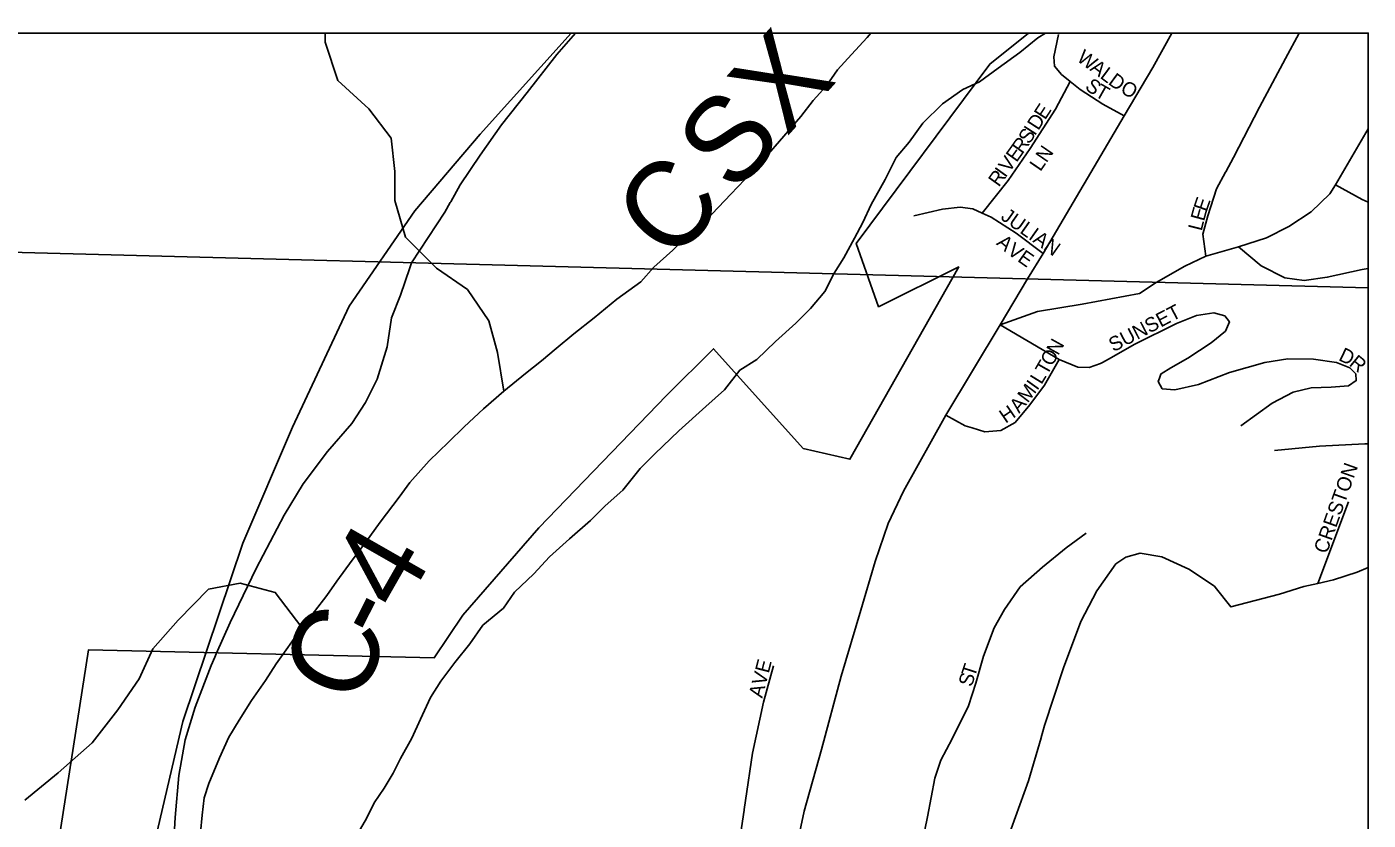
# Model space of a CAD drawing. Extents: x -84548 to 2262448, y -162180 to 525962.
# Drawn here: x 63175 to 67849, y 168130 to 170894 of the extents above; entities that cross this region are included whole.
import ezdxf

# ---------------------------------------------------------------- set-up
doc = ezdxf.new("R2010")
doc.units = 0
for name, color, linetype in [('GM_X_Corporation', 7, 'Continuous'), ('GM_X_County', 7, 'Continuous'), ('GM_X_County_Road', 7, 'Continuous'), ('GM_X_Hydro', 7, 'Continuous'), ('GM_X_Interstate_Location', 7, 'Continuous'), ('GM_X_Major_Lake_Text', 7, 'Continuous'), ('GM_X_Minor_River_Text', 7, 'Continuous'), ('GM_X_State_Route', 7, 'Continuous'), ('GM_X_Township_Subdivision_Text', 7, 'Continuous'), ('GM_X_Unincorporated_Location', 7, 'Continuous'), ('GM_X_US_Location', 7, 'Continuous'), ('GM_X_US_Route', 7, 'Continuous')]:
    doc.layers.add(name, color=color, linetype=linetype)

msp = doc.modelspace()

# ---------------------------------------------------------------- linework, layer by layer
at = {"layer": 'GM_X_County'}
for p, q in [((31945.4, 170872.5), (67849.4, 170872.5)), ((67849.4, 170872.5), (67849.4, 134968.5))]:
    msp.add_line(p, q, dxfattribs=at)
at = {"layer": 'GM_X_Hydro'}
msp.add_line((62491.5, 170125.7), (67849.4, 169984.2), dxfattribs=at)
at = {"layer": 'GM_X_Interstate_Location'}
for points in [[(64516.6, 168415.6), (64547.6, 168482.3), (64582.4, 168557.1), (64617.6, 168613.9), (64666.6, 168678.8), (64719.7, 168743.9), (64764.7, 168808.8), (64835.9, 168868.1), (64875, 168924.9), (64942.1, 168988.2), (64997.2, 169047.3), (65066.3, 169110.6), (65139.4, 169174), (65190.7, 169224.9), (65251.9, 169280.1), (65312.8, 169355.3), (65364, 169406.3), (65446.9, 169485.9), (65541.7, 169571.6), (65606.8, 169628.9), (65659.8, 169697.9), (65719.3, 169735), (65784.4, 169798.2), (65855.5, 169861.6), (65906.7, 169912.6), (65955.9, 169971.5), (65988.9, 170036.3), (66022.1, 170088.9), (66059.1, 170157.8), (66088.2, 170212.4), (66117.3, 170275.1), (66166, 170362.1), (66204.8, 170439), (66250, 170491.9), (66297.1, 170558.8), (66366.1, 170626.1), (66437.4, 170675.4), (66495, 170702.4), (66560.4, 170749.6), (66635.6, 170805), (66698.8, 170856.2), (66725.3, 170872.5)], [(66116.1, 170872.5), (66104.2, 170856.6), (66049, 170797.6), (65999.8, 170744.6), (65960.6, 170687.8), (65915.4, 170636.9), (65872.2, 170582.1), (65813.2, 170512.9), (65744.4, 170433.6), (65677.4, 170362.3), (65628.2, 170311.3), (65563.2, 170242.1), (65492.1, 170178.7), (65427, 170115.5), (65359.8, 170056.2), (65314.6, 170005.3), (65231.4, 169945.8), (65152.4, 169880.3), (65081.1, 169825), (65019.9, 169773.9), (64968.5, 169730.9), (64913.1, 169685.9)], [(64913.1, 169685.9), (64838, 169624.5), (64766.9, 169563.2), (64699.8, 169499.9), (64644.6, 169446.9), (64577.5, 169381.6), (64510.6, 169306.3), (64473.4, 169255.5), (64406.7, 169168.2), (64355.7, 169097.1), (64308.6, 169036.2), (64255.7, 168963.1), (64220.5, 168912.4), (64177.3, 168857.5), (64134.1, 168800.7), (64085.1, 168731.7), (64044, 168674.8), (64006.8, 168616.1), (63957.9, 168547), (63914.9, 168478.2), (63879.8, 168419.4), (63846.9, 168346.7), (63810.2, 168257.8), (63793, 168207.4), (63785.9, 168147.1), (63780.9, 168086.8)], [(64329.6, 168085.6), (64358.8, 168136.2), (64386, 168190.8), (64421.2, 168241.6), (64452.4, 168294.2), (64477.7, 168344.8), (64516.6, 168415.6)]]:
    msp.add_lwpolyline(points, dxfattribs=at)
at = {"layer": 'GM_X_Major_Lake_Text'}
msp.add_lwpolyline([(66091.5, 166671.9), (66031.4, 166747.7), (65948.4, 166868), (65891.6, 166973.8), (65846.9, 167057.6), (65841.5, 167237.8), (65846, 167426.1), (65842.2, 167658.4), (65844.8, 167832.7), (65849.7, 167998.1), (65884.3, 168161.5), (65944.7, 168376.3), (66012.8, 168631.2), (66081.1, 168862), (66131.8, 169030.7), (66176.8, 169163.2), (66230, 169275.8), (66377.7, 169540.7), (66566.6, 169855.9), (66662.7, 170015.6), (66716.4, 170104.7), (66999.5, 170583.9), (67099.2, 170752.6), (67165.1, 170872.5)], dxfattribs=at)
at = {"layer": 'GM_X_Minor_River_Text'}
for points in [[(64652.5, 170284.6), (64685.9, 170343.6), (64755.7, 170447.3), (64829.5, 170553), (64919.1, 170665.1), (65022.3, 170797.5), (65087.7, 170872.5)], [(64509.8, 170054.3), (64515.9, 170072.3), (64631.9, 170248.3), (64650.8, 170281.7), (64652.5, 170284.6)], [(63835.6, 168709.1), (63884.3, 168818.1), (63974.3, 169006.4), (64072.3, 169192.8), (64138, 169302.3), (64223.7, 169414.3), (64307.6, 169512.3), (64356, 169585.4), (64396.3, 169666.4), (64431.3, 169779.5), (64446, 169879.6), (64477.4, 169959.3), (64509.8, 170054.3)]]:
    msp.add_lwpolyline(points, dxfattribs=at)
at = {"layer": 'GM_X_State_Route'}
for points in [[(64838, 169624.5), (64815.1, 169759.9), (64785.2, 169870.2), (64711.2, 169978.5), (64603.2, 170052.7), (64495.2, 170161.1), (64457.3, 170289.5), (64457.3, 170389.8), (64445.3, 170506.1), (64367.3, 170608.4), (64259.4, 170706.7), (64215.4, 170841.1), (64215.4, 170872.5)], [(64134.1, 168800.7), (64041.1, 168923.3), (63919.1, 168955.4), (63809.1, 168935.3), (63703.1, 168827), (63615.1, 168726.7), (63567.1, 168622.4), (63493, 168514.1), (63403, 168399.7), (63285, 168295.4), (63169, 168199.1)]]:
    msp.add_lwpolyline(points, dxfattribs=at)
at = {"layer": 'GM_X_Township_Subdivision_Text'}
msp.add_lwpolyline([(67849.4, 159186.1), (67849.4, 170872.5), (66665.9, 170872.5), (66530.9, 170764.5), (66064.8, 170139.6), (66143.6, 169918.7), (66422.6, 170057.4), (66043.7, 169387.3), (65881.1, 169424.9), (65568, 169772.7), (65404.7, 169609.4), (64960, 169148.9), (64695, 168844), (64595.1, 168695.9), (63390, 168723.1), (63175.6, 167343.1), (63083.4, 167321.6), (63027, 167263.7), (62990.6, 167201.8), (61806.2, 167434.3), (60891.2, 167434.3), (60993.6, 168267), (60975.5, 168788.1), (57658.2, 168787.9)], dxfattribs=at)
at = {"layer": 'GM_X_Unincorporated_Location'}
msp.add_lwpolyline([(65797.8, 163683.4), (64931.5, 164490.9), (64776, 164625.2), (64522.4, 164772.8), (64164.9, 165001.2), (63947.4, 165219.4), (63665.8, 165488.3), (63484.8, 165649.3), (63354.2, 165815.8), (63299.3, 165969.2), (63259.3, 166117.3), (63278.1, 166434.9), (63339.6, 166846.8), (63719, 168473.8), (63928.7, 169095), (64101.1, 169498.7), (64298.3, 169920.8), (64528, 170252.9), (64755.1, 170520.2), (65072.7, 170872.5)], dxfattribs=at)
at = {"layer": 'GM_X_US_Location'}
for points in [[(66769.8, 170867.9), (66754.6, 170789.6), (66756.9, 170757.6), (66781.2, 170727.7), (66810.8, 170704.1), (66845.8, 170676.3), (66924.3, 170624.9), (66999.5, 170583.9)], [(67352.4, 170387.4), (67353.3, 170389.1), (67380.3, 170438.9), (67470.6, 170614.1), (67560.9, 170783.3), (67608.5, 170872.5)], [(66504.4, 170244.9), (66594.8, 170359.2), (66671.7, 170470.2), (66760.4, 170607.3), (66810.8, 170704.1)], [(66566.6, 169855.9), (66697.2, 169902.7), (66852.3, 169927.6), (67052.8, 169964.9), (67110.7, 170003.7), (67210, 170060.6), (67284, 170094.6), (67397.6, 170128.1), (67495.1, 170159.5), (67572.7, 170198.3), (67650.2, 170249.2), (67715.6, 170311.9), (67735, 170344), (67849.4, 170538.2)], [(67284, 170094.6), (67272.9, 170171.4), (67290.3, 170235.7), (67321.3, 170330.2), (67352.4, 170387.4)], [(67735, 170344), (67827.9, 170293), (67849.4, 170283.6)], [(66265.9, 170235.8), (66365.7, 170258.8), (66427.7, 170265.4), (66471.7, 170259.9), (66504.4, 170244.9), (66536.1, 170230.4), (66622.6, 170175.1), (66716.4, 170104.7)], [(67397.6, 170128.1), (67476, 170061.1), (67558.5, 170019.8), (67626.6, 170010.5), (67706.5, 170021.3), (67828.3, 170048.5), (67849.4, 170052)], [(66923.7, 169724.8), (66944.8, 169736.6), (67036.6, 169788.4), (67181.9, 169859.9), (67251.7, 169888.6), (67311.6, 169897.2), (67349.7, 169887.6), (67365.9, 169865.7), (67352.2, 169833.5), (67302.6, 169792.9), (67221.1, 169740.1), (67161.4, 169705.4), (67127.6, 169685.1), (67127, 169683.4)], [(66566.6, 169855.9), (66660.3, 169800.8), (66772.5, 169735.1), (66837.3, 169708.3), (66877.3, 169706.7), (66917.2, 169721.1), (66923.7, 169724.8)], [(66569.4, 169487.3), (66619.1, 169515.8), (66670.6, 169576.5), (66721.9, 169645.1), (66772.5, 169735.1)], [(67127, 169683.4), (67121.8, 169669.4), (67117.9, 169658.9), (67132.1, 169633), (67176.2, 169629.4), (67258, 169648.2), (67365.7, 169689.4), (67489.4, 169724.6), (67569.3, 169737.4), (67659.3, 169736.3), (67739.4, 169725), (67785.6, 169705.4), (67805.9, 169685.6), (67808.1, 169661.6), (67780.3, 169643.2), (67720.3, 169638.7), (67650.3, 169636), (67588.4, 169621.4), (67514.8, 169582.6), (67405.5, 169503.4)], [(66377.7, 169540.7), (66445.2, 169504.1), (66469.5, 169496.5)], [(66469.5, 169496.5), (66469.6, 169496.5), (66513.4, 169482.8), (66569.4, 169487.3)], [(67522.4, 169418.3), (67679.5, 169432.8), (67837.5, 169441.7), (67849.4, 169440.9)], [(67673.4, 168955.1), (67780.3, 169238.5)], [(66360.5, 168338.6), (66360.7, 168339.1), (66400, 168413.6), (66456.9, 168528.4), (66482.1, 168606.8), (66509.2, 168701.2), (66546.2, 168799.8), (66581.6, 168864.2), (66636.8, 168942.9), (66714.1, 169011.8), (66797.5, 169078.7), (66867, 169129.5)], [(66709.5, 168416.4), (66709.9, 168418), (66722.1, 168459.9), (66788.1, 168661), (66848.6, 168821.9), (66903.5, 168928.6), (66970.6, 169023.5), (67004.4, 169045.9), (67054.3, 169060.4), (67130.5, 169047.1), (67225, 169003.9), (67313.7, 168944.7), (67316.3, 168941.4)], [(67540.2, 168916.8), (67625.1, 168944.4), (67673.4, 168955.1), (67728.9, 168967.5), (67810.7, 168994.3), (67849.4, 169009.8)], [(67316.3, 168941.4), (67370.5, 168873.1), (67540.2, 168916.8)], [(63630.5, 167376.1), (63639.4, 167456.7), (63655.4, 167641.4), (63675.2, 167840.1), (63683.9, 167994.6), (63692.8, 168139), (63705.6, 168285.5), (63727, 168410.2), (63762.6, 168523.1), (63817.5, 168668.5), (63830.8, 168698.4), (63835.6, 168709.1)], [(65675.2, 168166.8), (65679.9, 168198.3), (65704.2, 168362.8), (65742.5, 168541.5), (65777.2, 168668.1)], [(66489.4, 166938.5), (66468.8, 166994.4), (66397.6, 167106), (66350.5, 167209.7), (66337.9, 167267.7), (66343.2, 167331.9), (66348.3, 167349.3), (66370.3, 167424.4), (66446.1, 167643.6), (66479.5, 167738.9), (66507.3, 167818.3), (66512.3, 167832.6), (66605.7, 168100), (66666, 168267), (66709.5, 168416.4)], [(66313.7, 168141.4), (66339.3, 168276.8), (66360.5, 168338.6)], [(65611.1, 166863), (65596.6, 166909), (65601.6, 167007.2), (65616.6, 167309.9), (65629.6, 167580.3), (65629.9, 167586.6), (65648.7, 167905.4), (65655, 168025.5), (65655.5, 168033.7), (65675, 168165.3), (65675.2, 168166.8)], [(66243, 167793), (66243, 167793.2), (66254.8, 167850), (66265, 167899.3), (66305.1, 168096.1), (66313.6, 168141.3), (66313.7, 168141.4)]]:
    msp.add_lwpolyline(points, dxfattribs=at)

# ---------------------------------------------------------------- texts
at = {"layer": 'GM_X_Corporation'}
for s, rotation, p in [('X', 47.9756, (65823.1, 170509.2)), ('S', 47.9739, (65640.5, 170306.5)), ('C', 47.9764, (65422.5, 170064.6))]:
    msp.add_text(s, height=298.1, rotation=rotation, dxfattribs=at).set_placement(p)
at = {"layer": 'GM_X_County_Road'}
for s, rotation, p in [('4', 60.2532, (64479.4, 168847.2)), ('-', 63.037, (64425.4, 168740.8)), ('C', 65.3745, (64324.1, 168519.7))]:
    msp.add_text(s, height=300, rotation=rotation, dxfattribs=at).set_placement(p)
at = {"layer": 'GM_X_US_Route'}
for s, rotation, p in [('W', 323.4226, (66830.9, 170778)), ('A', 323.4142, (66876.9, 170743.9)), ('L', 323.4095, (66912.2, 170717.7)), ('S', 322.6055, (66859.3, 170679.8)), ('T', 330.462, (66893.5, 170654.3)), ('D', 323.4257, (66940.5, 170696.7)), ('O', 332.0501, (66982.7, 170666.1)), ('E', 57.1633, (66723.6, 170567.5)), ('I', 57.1374, (66687.8, 170512.1)), ('D', 57.1641, (66699.8, 170530.6)), ('R', 54.8683, (66644.5, 170448.5)), ('S', 56.7264, (66668.3, 170482.3)), ('E', 54.4384, (66623.8, 170419.5)), ('LN', 55.498, (66707.1, 170387.5)), ('V', 54.4217, (66598.2, 170383.7)), ('R', 54.4101, (66562.3, 170333.6)), ('I', 54.4064, (66585.4, 170365.8)), ('E', 71.1374, (67286.7, 170247.6)), ('JULIAN', 324.7279, (66565.8, 170225.6)), ('E', 74.6814, (67277.6, 170214.5)), ('L', 76.1493, (67269.3, 170180.6)), ('A', 319.2458, (66551.2, 170137.2)), ('V', 324.1875, (66588.2, 170105.6)), ('E', 324.9192, (66624.5, 170079.4)), ('SUNSET', 27.5529, (66961.7, 169760)), ('N', 60.922, (66769.1, 169746.7)), ('O', 60.955, (66747.7, 169708.3)), ('D', 334.5103, (67743.3, 169733.7)), ('T', 60.3995, (66730.1, 169677.2)), ('R', 320.4184, (67780.2, 169716.6)), ('I', 54.5483, (66695.9, 169624.7)), ('L', 58.2985, (66710.6, 169645.5)), ('M', 52.7638, (66662.9, 169581.2)), ('H', 34.4781, (66585.9, 169510.6)), ('A', 50.189, (66633.2, 169545.5)), ('CRESTON', 70.4078, (67705.2, 169055.4)), ('AVE', 75.4658, (65738.1, 168553.1)), ('S', 73.6305, (66468.4, 168592.1)), ('T', 71.8286, (66478.2, 168625.4))]:
    msp.add_text(s, height=50, rotation=rotation, dxfattribs=at).set_placement(p)

doc.saveas('drawing.dxf')
